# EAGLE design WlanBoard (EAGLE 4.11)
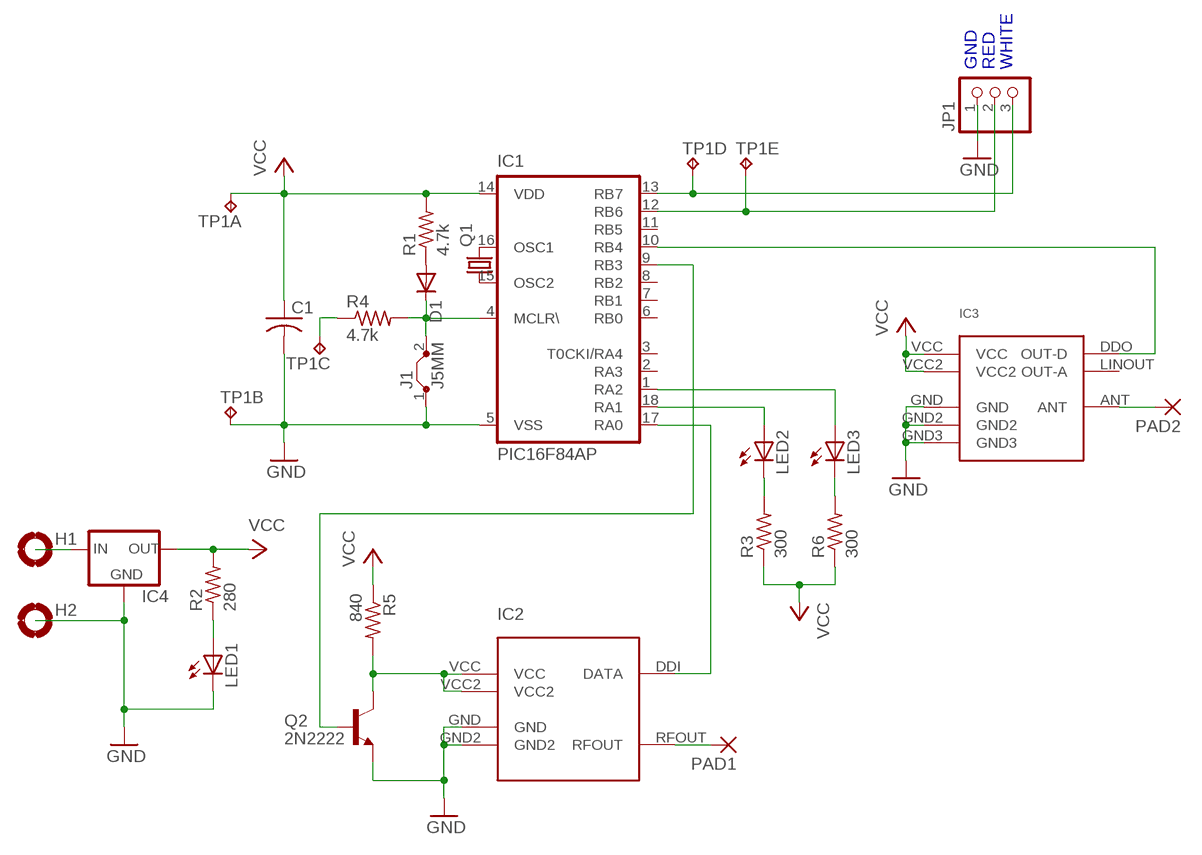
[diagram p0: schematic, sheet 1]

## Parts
C1  C-US025-025X050  [C025-025X050]
D1  DIODE-D-5  [D-5]
H1  MOUNT-PAD-ROUND3.0  [3,0-PAD]
H2  MOUNT-PAD-ROUND3.0  [3,0-PAD]
IC1  PIC16F84AP  [DIL18]
IC2  433.62MHz  TX433  [TX433-6]
IC3  433.62MHz  RX433  [RX433-10]
IC4  78XXL  [78XXL]
J1  J5MM  [05]
JP1  PINHD-1X3  [1X03]
LED1  LED3MM  [LED3MM]
LED2  LED3MM  [LED3MM]
LED3  LED3MM  [LED3MM]
PAD1  2,54/0,8  [2,54/0,8]
PAD2  2,54/0,8  [2,54/0,8]
Q1  CRYTALHC18U-V  [HC18U-V]
Q2  2N2222  [TO18]
R1  4.7k  R-US_0204/7  [0204/7]
R2  280  R-US_0204/7  [0204/7]
R3  300  R-US_0204/7  [0204/7]
R4  4.7k  R-US_0204/7  [0204/7]
R5  840  R-US_0204/7  [0204/7]
R6  300  R-US_0204/7  [0204/7]
TP1  TP5P5-25-13  [P5-25-13]

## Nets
GND: C1.2 H2.B3,0(MOUNT) IC1.5(VSS) IC2.GND IC2.GND2 IC3.GND IC3.GND2 IC3.GND3 IC4.GND J1.1 JP1.1 LED1.K(C) Q2.1(E) TP1.2
N$1: IC1.16(OSC1) Q1.2
N$2: IC1.15(OSC2) Q1.1
N$3: LED1.A R2.1
N$4: IC1.13(RB7) JP1.3 TP1.4
N$5: IC1.17(RA0) IC2.DDI(DATA)
N$6: IC2.RFOUT PAD1.1(P)
N$8: LED3.K(C) R6.2
N$9: IC1.12(RB6) JP1.2 TP1.5
N$10: IC1.10(RB4) IC3.DDO(OUT-D)
N$11: IC3.ANT PAD2.1(P)
N$12: IC1.18(RA1) LED2.A
N$13: IC1.1(RA2) LED3.A
N$14: R4.1 TP1.3
N$15: D1.A R1.1
N$17: H1.B3,0(MOUNT) IC4.IN
N$20: IC2.VCC IC2.VCC2 Q2.3(C) R5.2
N$21: IC1.9(RB3) Q2.2(B)
N$32: D1.C IC1.4(MCLR\) J1.2 R4.2
N$34: LED2.K(C) R3.2
VCC: C1.1 IC1.14(VDD) IC3.VCC IC3.VCC2 IC4.OUT R1.2 R2.2 R3.1 R5.1 R6.1 TP1.1
Unconnected: IC1.2(RA3) IC1.3(T0CKI/RA4) IC1.6(RB0) IC1.7(RB1) IC1.8(RB2) IC1.11(RB5) IC3.LINOUT(OUT-A)

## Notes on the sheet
- GND | RED | WHITE

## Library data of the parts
C1 = rcl:C-US: CAPACITOR, American symbol
D1 = diode:DIODE-: DIODE
H1 H2 = holes:MOUNT-PAD-ROUND: MOUNTING PAD, round
IC1 = microchip:PIC16F8*: MICROCONTROLLER 8-Bit PIC16F8X Family - CMOS Flash/EEPROM Pin Compatible : PIC16F83, PIC16CR83, PIC16F84A, PIC16CR84 see also PIC16C*
IC2 = wireless:TX433
IC3 = wireless:RX433
IC4 = v-reg:78XXL: VOLTAGE REGULATOR
J1 = jumper:J: Bridge
JP1 = pinhead:PINHD-1X3: PIN HEADER
LED1-LED3 = led:LED: LED
PAD1 PAD2 = wirepad:2,54/0,8: THROUGH-HOLE PAD
Q1 = crystal:CRYTAL: CRYSTAL
Q2 = transistor-npn:2N2222*: NPN Transistor
R1-R6 = rcl:R-US_: RESISTOR, American symbol
TP1 = testpad:TP5

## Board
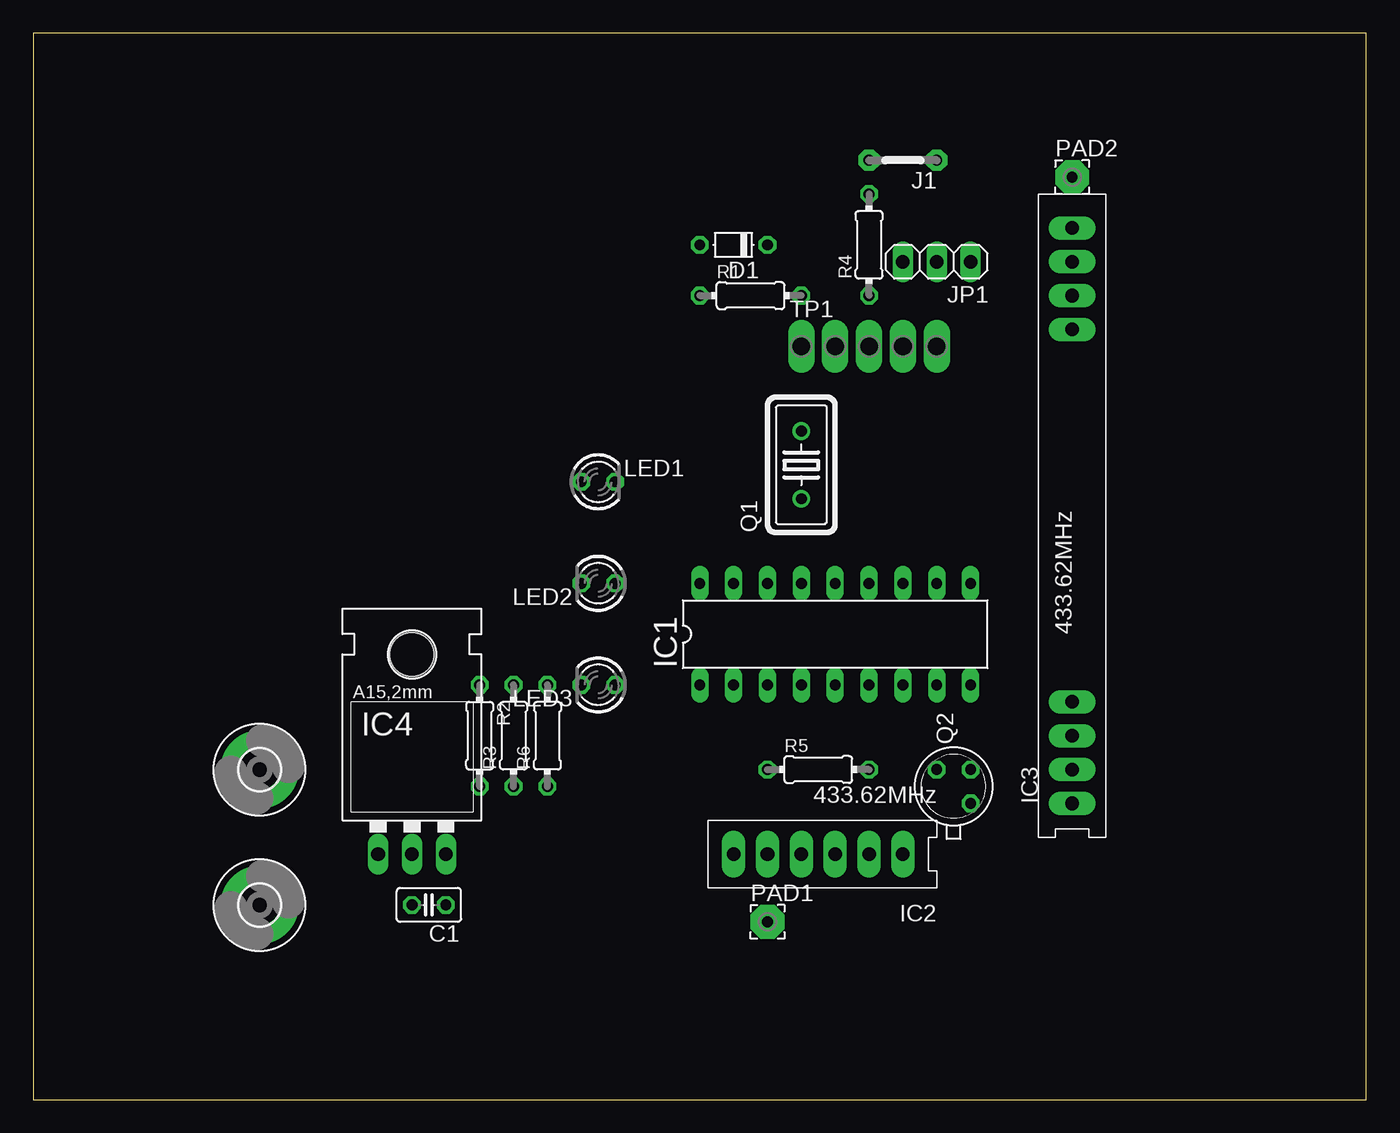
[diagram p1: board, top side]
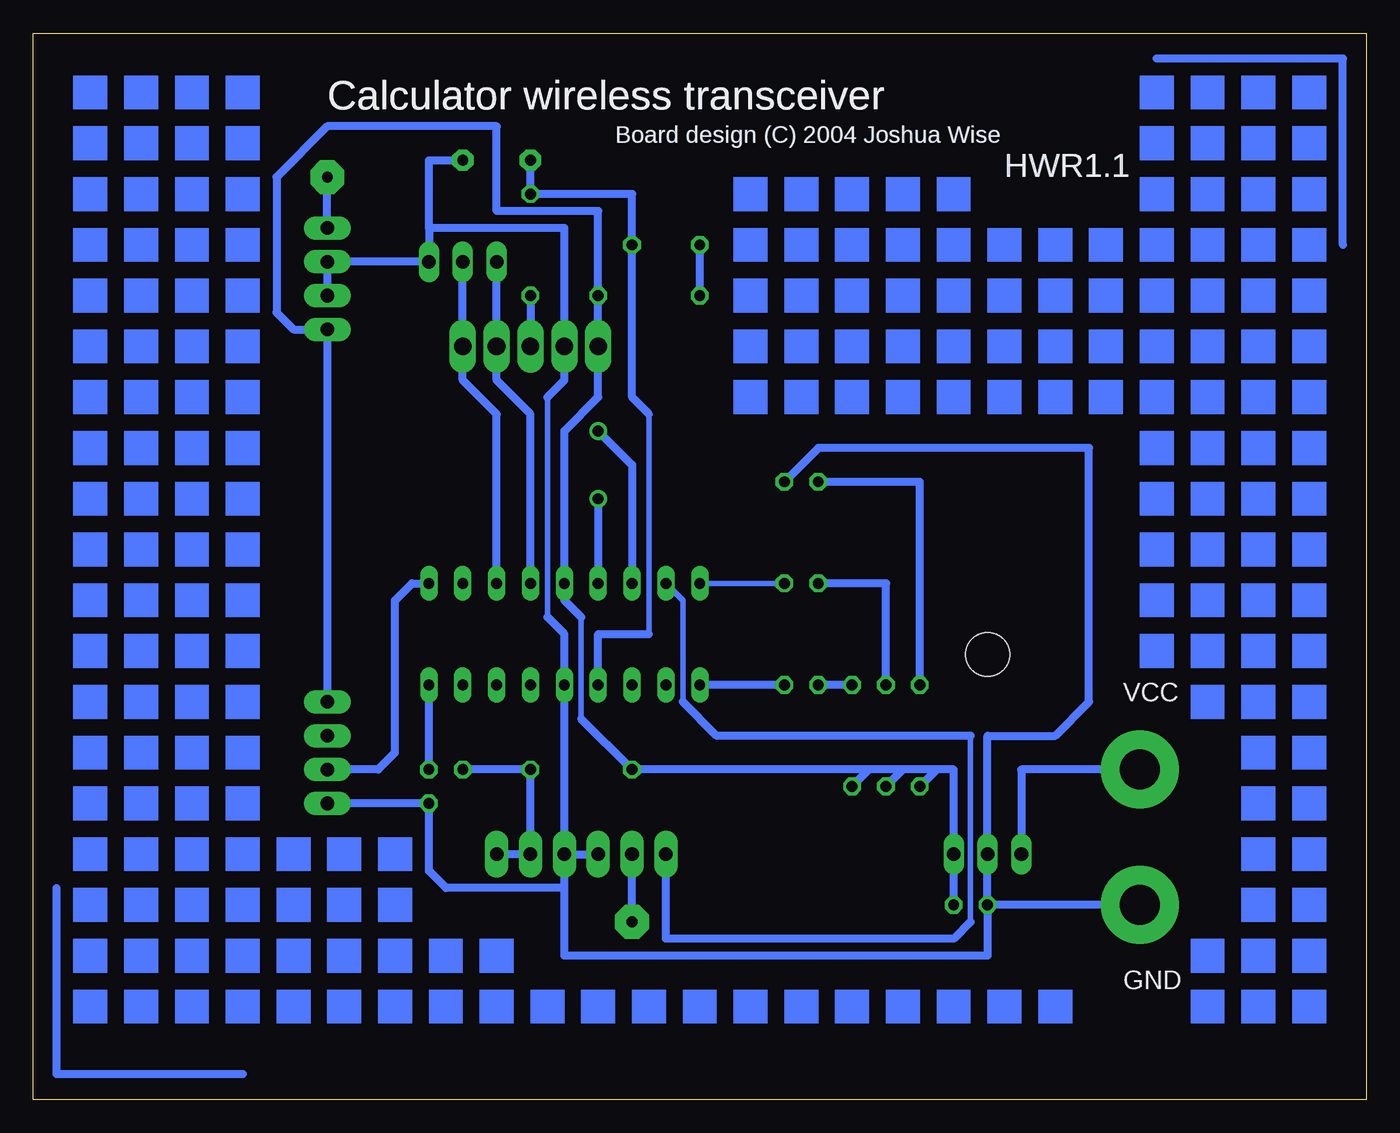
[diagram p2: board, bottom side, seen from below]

Size 100 x 80 mm. Coordinates in mm from the lower left corner, seen from the top.
Outline: 0,0 100,0 100,80 0,80 0,0
Copper layers (1*16): Top 0.035mm / dielectric 1.5mm / Bottom 0.035mm
Design rules "default": minimum track width 10mil, minimum drill 24mil, track to track 8mil, track to pad 8mil, pad to pad 8mil, via to via 8mil, smd to smd 8mil, copper to edge 40mil, drill to drill 8mil, minimum pad ring 10mil, minimum via ring 8mil, stop-mask expansion 4mil, vias tented up to drill 0mil, thermal gap 10mil

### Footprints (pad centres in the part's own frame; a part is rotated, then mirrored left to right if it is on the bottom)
C025-025X050 = drill 0.813 octagon: 1 -1.27,0; 2 1.27,0
D-5 = drill 0.813 octagon: A 2.54,0; C -2.54,0
3,0-PAD = drill 3 pad 5.842 round: B3,0 0,0
DIL18 = drill 0.813 long: 1 -10.16,-3.81; 2 -7.62,-3.81; 3 -5.08,-3.81; 4 -2.54,-3.81; 5 0,-3.81; 6 2.54,-3.81; 7 5.08,-3.81; 8 7.62,-3.81; 9 10.16,-3.81; 10 10.16,3.81; 11 7.62,3.81; 12 5.08,3.81; 13 2.54,3.81; 14 0,3.81; 15 -2.54,3.81; 16 -5.08,3.81; 17 -7.62,3.81; 18 -10.16,3.81
TX433-6 = drill 1.016 pad 1.778 long: DDI 12.7,0; GND 5.08,0; GND2 7.62,0; RFOUT 10.16,0; VCC 0,0; VCC2 2.54,0
RX433-10 = drill 1.016 pad 1.778 long: ANT 43.18,0; DDO 2.54,0; GND 0,0; GND2 38.1,0; GND3 40.64,0; LINOUT 5.08,0; VCC 7.62,0; VCC2 35.56,0
78XXL = drill 1.016 long: GND 0,-3.81; IN -2.54,-3.81; OUT 2.54,-3.81 | hole 3.302: 0,11.176
05 = drill 0.813 pad 1.6 octagon: 1 -2.54,0; 2 2.54,0
1X03 = drill 1.016 long: 1 -2.54,0; 2 0,0; 3 2.54,0
LED3MM = drill 0.813 octagon: A -1.27,0; K 1.27,0
2,54/0,8 = drill 0.813 pad 2.54 octagon: 1 0,0
HC18U-V = drill 0.813 round: 1 -2.54,0; 2 2.54,0
TO18 = drill 0.813 octagon: 1 -1.27,-1.27; 2 1.27,-1.27; 3 1.27,1.27
0204/7 = drill 0.813 octagon: 1 -3.81,0; 2 3.81,0
P5-25-13 = drill 1.321 pad 1.905 long: 1 -5.08,0; 2 -2.54,0; 3 0,0; 4 2.54,0; 5 5.08,0

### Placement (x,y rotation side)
C1  29.68,14.6 180 top
D1  52.54,64.13 180 top
H1  16.98,24.76 0 top
H2  16.98,14.6 0 top
IC1  60.16,34.92 0 top
IC2  65.24,18.41 180 top
IC3  77.94,22.22 90 top
IC4  28.41,22.22 0 top
J1  65.24,70.48 180 top
JP1  67.78,62.86 180 top
LED1  42.38,46.35 0 top
LED2  42.38,38.73 180 top
LED3  42.38,31.11 180 top
PAD1  55.08,13.33 0 top
PAD2  77.94,69.21 0 top
Q1  57.62,47.62 90 top
Q2  69.05,23.49 90 top
R1  53.81,60.32 0 top
R2  33.49,27.3 270 top
R3  36.03,27.3 90 top
R4  62.7,64.13 90 top
R5  58.89,24.76 0 top
R6  38.57,27.3 90 top
TP1  62.7,56.51 0 top

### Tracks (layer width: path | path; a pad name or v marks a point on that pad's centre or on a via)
ALIGNMENT
  Bottom 0.61: 15.71,78.1 1.74,78.1 1.74,64.13
GND
  Bottom 0.406: 61.43,36.19 61.43,52.7
  Bottom 0.61: 70.32,65.4 70.32,70.48 J1.1 | 60.16,15.87 69.05,15.87 70.32,17.14 Q2.1 IC3.GND | C1.2 IC4.GND 28.41,27.3 23.33,27.3 20.79,29.84 20.79,48.89 41.11,48.89 LED1.K | H2.B3,0 C1.2 | C1.2 28.41,10.79 60.16,10.79 60.16,15.87 | IC2.GND IC1.5 60.16,34.92 61.43,36.19 | 61.43,52.7 60.16,53.97 TP1.2 60.16,65.4 70.32,65.4 | 70.32,65.4 JP1.1 IC3.GND3 IC3.GND2 | IC2.GND IC2.GND2 | 60.16,15.87 IC2.GND
N$1
  Bottom 0.61: Q1.2 55.08,47.62 IC1.16
N$2
  Bottom 0.61: Q1.1 IC1.15
N$3
  Bottom 0.61: R2.1 33.49,46.35 LED1.A
N$4
  Bottom 0.61: IC1.13 62.7,51.43 65.24,53.97 TP1.4 JP1.3
N$5
  Bottom 0.406: 29.68,13.33 29.68,27.3 | 51.27,29.84 51.27,37.46 IC1.17
  Bottom 0.61: 29.68,13.33 30.95,12.06 52.54,12.06 IC2.DDI | 29.68,27.3 48.73,27.3 51.27,29.84
N$6
  Bottom 0.61: PAD1.1 IC2.RFOUT
N$7
  Bottom 0.61: 98.26,15.87 98.26,1.9 84.29,1.9
N$8
  Bottom 0.61: R6.2 LED3.K
N$9
  Bottom 0.61: IC1.12 65.24,51.43 67.78,53.97 TP1.5 JP1.2
N$10
  Bottom 0.406: 77.79,24.76 IC3.DDO
  Bottom 0.61: 77.79,24.76 74.13,24.76 72.86,26.03 72.86,37.46 71.59,38.73 IC1.10
N$11
  Bottom 0.61: IC3.ANT PAD2.1
N$12
  Bottom 0.406: LED2.A IC1.18
N$13
  Bottom 0.61: LED3.A IC1.1
N$14
  Bottom 0.61: R4.1 TP1.3
N$15
  Bottom 0.61: R1.1 D1.A
N$17
  Bottom 0.61: H1.B3,0 25.87,24.76 IC4.IN
N$20
  Bottom 0.61: IC2.VCC IC2.VCC2 R5.2 Q2.3
N$21
  Bottom 0.61: Q2.2 IC1.9
N$32
  Bottom 0.406: 53.81,34.92 53.81,51.43
  Bottom 0.61: IC1.4 57.62,34.92 53.81,34.92 | 53.81,51.43 55.08,52.7 D1.C 55.08,67.94 R4.2 J1.2
N$34
  Bottom 0.61: LED2.K 36.03,38.73 R3.2
VCC
  Bottom 0.406: 58.89,28.57 58.89,36.19
  Bottom 0.61: IC3.VCC IC3.VCC2 80.48,57.78 81.75,59.05 81.75,69.21 77.94,73.02 65.24,73.02 65.24,66.67 57.62,66.67 R1.2 TP1.1 57.62,52.7 60.16,50.16 IC1.14 60.16,37.46 58.89,36.19 | 58.89,28.57 R5.1 37.3,24.76 | C1.1 IC4.OUT 30.95,24.76 32.22,24.76 | 34.76,24.76 37.3,24.76 | 34.76,24.76 R3.1 | 37.3,24.76 R6.1 | 32.22,24.76 34.76,24.76 | 32.22,24.76 R2.2
(copper drawn outside any net)
  shapes: Bottom area x205

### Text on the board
Bottom: Calculator wireless transceiver | Board design (C) 2004 Joshua Wise | HWR1.1
bNames: Calculator wireless transceiver | Calculator wireless transceiver | Board design (C) 2004 Joshua Wise | HWR1.1 | VCC | GND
